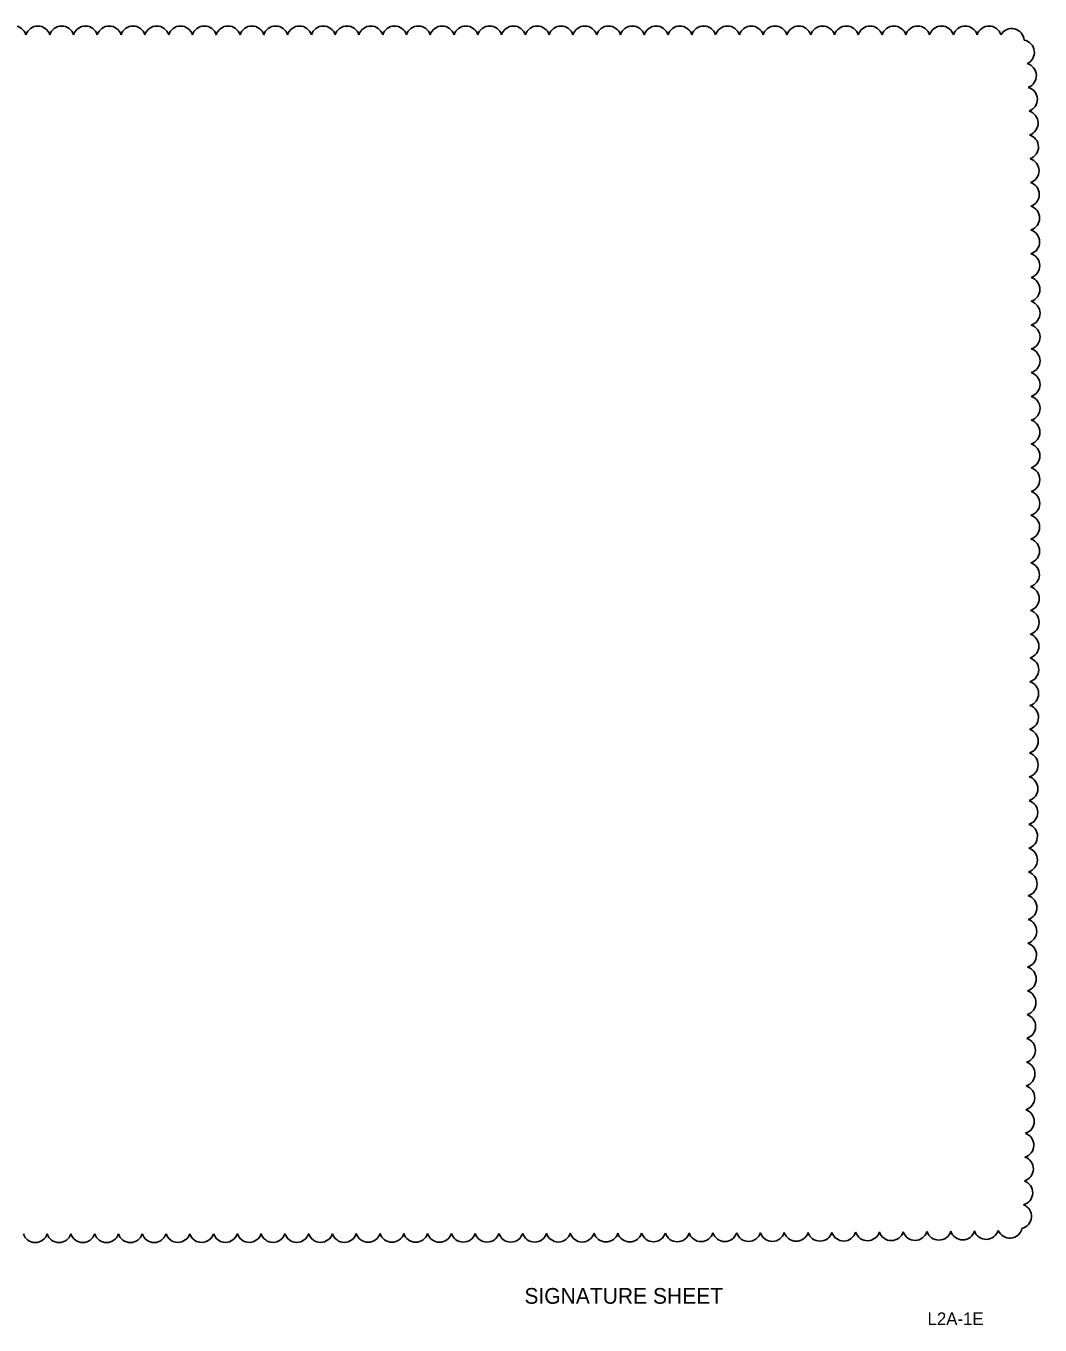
# Model space of a CAD drawing. Extents: x -811 to -790, y -2284 to -2178.
# Drawn here: x -803.16 to -795.1, y -2258.09 to -2247.76 of the extents above; entities that cross this region are included whole.
import ezdxf

# ---------------------------------------------------------------- set-up
doc = ezdxf.new("R2010")
doc.units = 0
for name, color, linetype in [('PlotBorder_dp', 7, 'Continuous'), ('ScratchEle_dp', 7, 'Continuous'), ('SheetLines_dp', 7, 'Continuous')]:
    doc.layers.add(name, color=color, linetype=linetype)

msp = doc.modelspace()

# ---------------------------------------------------------------- linework, layer by layer
at = {"layer": 'ScratchEle_dp'}
for centre, radius, start, end in [((-803.255, -2247.864), 0.0991, 17.5008, 162.5008), ((-803.066, -2247.864), 0.0991, 17.5, 162.5), ((-802.877, -2247.864), 0.0991, 17.5, 162.5), ((-802.688, -2247.864), 0.0991, 17.5, 162.5), ((-802.499, -2247.864), 0.0991, 17.5, 162.5), ((-802.31, -2247.864), 0.0991, 17.5, 162.5), ((-802.121, -2247.864), 0.0991, 17.5, 162.5), ((-801.932, -2247.864), 0.0991, 17.5, 162.5), ((-801.743, -2247.864), 0.0991, 17.5, 162.5), ((-801.554, -2247.864), 0.0991, 17.5, 162.5), ((-801.365, -2247.864), 0.0991, 17.5, 162.5), ((-801.176, -2247.864), 0.0991, 17.5, 162.5), ((-800.987, -2247.864), 0.0991, 17.5, 162.5), ((-800.798, -2247.864), 0.0991, 17.5, 162.5), ((-800.609, -2247.864), 0.0991, 17.5, 162.5), ((-800.42, -2247.864), 0.0991, 17.5, 162.5), ((-800.231, -2247.864), 0.0991, 17.5, 162.5), ((-800.042, -2247.864), 0.0991, 17.5, 162.5), ((-799.853, -2247.864), 0.0991, 17.5, 162.5), ((-799.664, -2247.864), 0.0991, 17.5, 162.5), ((-799.475, -2247.864), 0.0991, 17.5, 162.5), ((-799.286, -2247.864), 0.0991, 17.5, 162.5), ((-799.097, -2247.864), 0.0991, 17.5, 162.5), ((-798.908, -2247.864), 0.0991, 17.5, 162.5), ((-798.719, -2247.864), 0.0991, 17.5, 162.5), ((-798.53, -2247.864), 0.0991, 17.5, 162.5), ((-798.341, -2247.864), 0.0991, 17.5, 162.5), ((-798.152, -2247.864), 0.0991, 17.5, 162.5), ((-797.963, -2247.864), 0.0991, 17.5, 162.5), ((-797.774, -2247.864), 0.0991, 17.5, 162.5), ((-797.585, -2247.864), 0.0991, 17.5, 162.5), ((-797.396, -2247.864), 0.0991, 17.5, 162.5), ((-797.207, -2247.864), 0.0991, 17.5, 162.5), ((-797.018, -2247.864), 0.0991, 17.5, 162.5), ((-796.829, -2247.864), 0.0991, 17.5, 162.5), ((-796.64, -2247.864), 0.0991, 17.5, 162.5), ((-796.451, -2247.864), 0.0991, 17.5, 162.5), ((-796.262, -2247.864), 0.0991, 17.5, 162.5), ((-796.073, -2247.864), 0.0991, 17.5, 162.5), ((-795.884, -2247.864), 0.0991, 17.5, 162.5), ((-795.695, -2247.864), 0.0991, 17.5, 162.5), ((-795.506, -2247.864), 0.0991, 17.5, 162.5), ((-795.326, -2247.884), 0.099, 4.4162, 149.4162), ((-795.245, -2247.974), 0.0992, 294.7802, 79.7802), ((-795.229, -2248.16), 0.0991, 290.3649, 75.3649), ((-795.221, -2248.348), 0.0991, 289.3839, 74.3839), ((-795.215, -2248.537), 0.0991, 288.8712, 73.8712), ((-795.212, -2248.726), 0.0991, 288.5423, 73.5423), ((-795.208, -2248.915), 0.0991, 288.3081, 73.3081), ((-795.206, -2249.104), 0.0991, 288.1304, 73.1304), ((-795.204, -2249.292), 0.0991, 287.9896, 72.9896), ((-795.203, -2249.481), 0.0991, 287.8744, 72.8744), ((-795.202, -2249.67), 0.0991, 287.778, 72.778), ((-795.201, -2249.859), 0.0991, 287.6956, 72.6956), ((-795.2, -2250.048), 0.0991, 287.6243, 72.6243), ((-795.2, -2250.237), 0.0991, 287.5617, 72.5617), ((-795.2, -2250.426), 0.0991, 287.5062, 72.5062), ((-795.2, -2250.615), 0.0991, 287.4565, 72.4565), ((-795.2, -2250.804), 0.0991, 287.4117, 72.4117), ((-795.201, -2250.993), 0.0991, 287.3711, 72.3711), ((-795.201, -2251.182), 0.0991, 287.3339, 72.3339), ((-795.202, -2251.371), 0.0991, 287.2999, 72.2999), ((-795.202, -2251.56), 0.0991, 287.2684, 72.2684), ((-795.203, -2251.749), 0.0991, 287.2394, 72.2394), ((-795.204, -2251.938), 0.0991, 287.2123, 72.2123), ((-795.205, -2252.127), 0.0991, 287.1871, 72.1871), ((-795.206, -2252.316), 0.0991, 287.1635, 72.1635), ((-795.207, -2252.505), 0.0991, 287.1414, 72.1414), ((-795.209, -2252.694), 0.0991, 287.126, 72.126), ((-795.21, -2252.883), 0.0991, 287.1162, 72.1162), ((-795.211, -2253.072), 0.0991, 287.1058, 72.1058), ((-795.212, -2253.261), 0.0991, 287.0946, 72.0946), ((-795.214, -2253.45), 0.0991, 287.0827, 72.0827), ((-795.215, -2253.639), 0.0991, 287.0698, 72.0698), ((-795.217, -2253.828), 0.0991, 287.0559, 72.0559), ((-795.218, -2254.017), 0.0991, 287.0408, 72.0408), ((-795.22, -2254.206), 0.0991, 287.0244, 72.0244), ((-795.221, -2254.395), 0.0991, 287.0064, 72.0064), ((-795.223, -2254.584), 0.0991, 286.9865, 71.9865), ((-795.225, -2254.773), 0.0991, 286.9645, 71.9645), ((-795.226, -2254.962), 0.0991, 286.94, 71.94), ((-795.228, -2255.151), 0.0991, 286.9123, 71.9123), ((-795.23, -2255.34), 0.0991, 286.8807, 71.8807), ((-795.232, -2255.529), 0.0991, 286.8443, 71.8443), ((-795.235, -2255.718), 0.0991, 286.8016, 71.8016), ((-795.237, -2255.907), 0.0991, 286.7507, 71.7507), ((-795.24, -2256.096), 0.0991, 286.6884, 71.6884), ((-795.242, -2256.285), 0.0991, 286.6098, 71.6098), ((-795.246, -2256.473), 0.0991, 286.5063, 71.5063), ((-795.249, -2256.662), 0.0991, 286.3609, 71.3609), ((-795.253, -2256.851), 0.0991, 286.1344, 71.1344), ((-795.258, -2257.04), 0.0991, 285.7012, 70.7012), ((-795.268, -2257.228), 0.099, 283.7418, 68.7418), ((-803.087, -2257.337), 0.0991, 197.4952, 342.4952), ((-802.898, -2257.337), 0.0991, 197.5007, 342.5007), ((-802.709, -2257.337), 0.0991, 197.5043, 342.5043), ((-802.52, -2257.337), 0.0991, 197.5079, 342.5079), ((-802.331, -2257.337), 0.0991, 197.5117, 342.5117), ((-802.142, -2257.337), 0.0991, 197.5156, 342.5156), ((-801.953, -2257.336), 0.0991, 197.5197, 342.5197), ((-801.764, -2257.336), 0.0991, 197.5239, 342.5239), ((-801.575, -2257.336), 0.0991, 197.5284, 342.5284), ((-801.386, -2257.336), 0.0991, 197.533, 342.533), ((-801.197, -2257.336), 0.0991, 197.5379, 342.5379), ((-801.008, -2257.336), 0.0991, 197.543, 342.543), ((-800.819, -2257.336), 0.0991, 197.5483, 342.5483), ((-800.63, -2257.336), 0.0991, 197.554, 342.554), ((-800.441, -2257.335), 0.0991, 197.5599, 342.5599), ((-800.252, -2257.335), 0.0991, 197.5662, 342.5662), ((-800.063, -2257.335), 0.0991, 197.5729, 342.5729), ((-799.874, -2257.335), 0.0991, 197.5799, 342.5799), ((-799.685, -2257.334), 0.0991, 197.5874, 342.5874), ((-799.496, -2257.334), 0.0991, 197.5954, 342.5954), ((-799.307, -2257.334), 0.0991, 197.604, 342.604), ((-799.118, -2257.334), 0.0991, 197.6131, 342.6131), ((-798.929, -2257.333), 0.0991, 197.623, 342.623), ((-798.74, -2257.333), 0.0991, 197.6337, 342.6337), ((-798.551, -2257.332), 0.0991, 197.6452, 342.6452), ((-798.362, -2257.332), 0.0991, 197.6578, 342.6578), ((-798.173, -2257.331), 0.0991, 197.6716, 342.6716), ((-797.984, -2257.331), 0.0991, 197.6868, 342.6868), ((-797.795, -2257.33), 0.0991, 197.7037, 342.7037), ((-797.606, -2257.329), 0.0991, 197.7225, 342.7225), ((-797.417, -2257.328), 0.0991, 197.7438, 342.7438), ((-797.228, -2257.328), 0.0991, 197.768, 342.768), ((-797.039, -2257.327), 0.0991, 197.796, 342.796), ((-796.85, -2257.326), 0.0991, 197.8288, 342.8288), ((-796.661, -2257.325), 0.0991, 197.8681, 342.8681), ((-796.472, -2257.323), 0.0991, 197.9161, 342.9161), ((-796.283, -2257.322), 0.0991, 197.9767, 342.9767), ((-796.094, -2257.32), 0.0991, 198.0568, 343.0568), ((-795.905, -2257.318), 0.0991, 198.1697, 343.1697), ((-795.716, -2257.316), 0.0991, 198.3466, 343.3466), ((-795.528, -2257.312), 0.0991, 198.6898, 343.6898), ((-795.341, -2257.302), 0.0992, 202.4244, 347.4244)]:
    msp.add_arc(centre, radius, start, end, dxfattribs=at)

# ---------------------------------------------------------------- texts
at = {"layer": 'PlotBorder_dp'}
msp.add_text('       SIGNATURE SHEET         ', height=0.125, dxfattribs=at).set_placement((-799.524, -2257.923))
at = {"layer": 'SheetLines_dp'}
msp.add_text('L2A-1E', height=0.1, dxfattribs=at).set_placement((-795.995, -2258.092))

doc.saveas('drawing.dxf')
